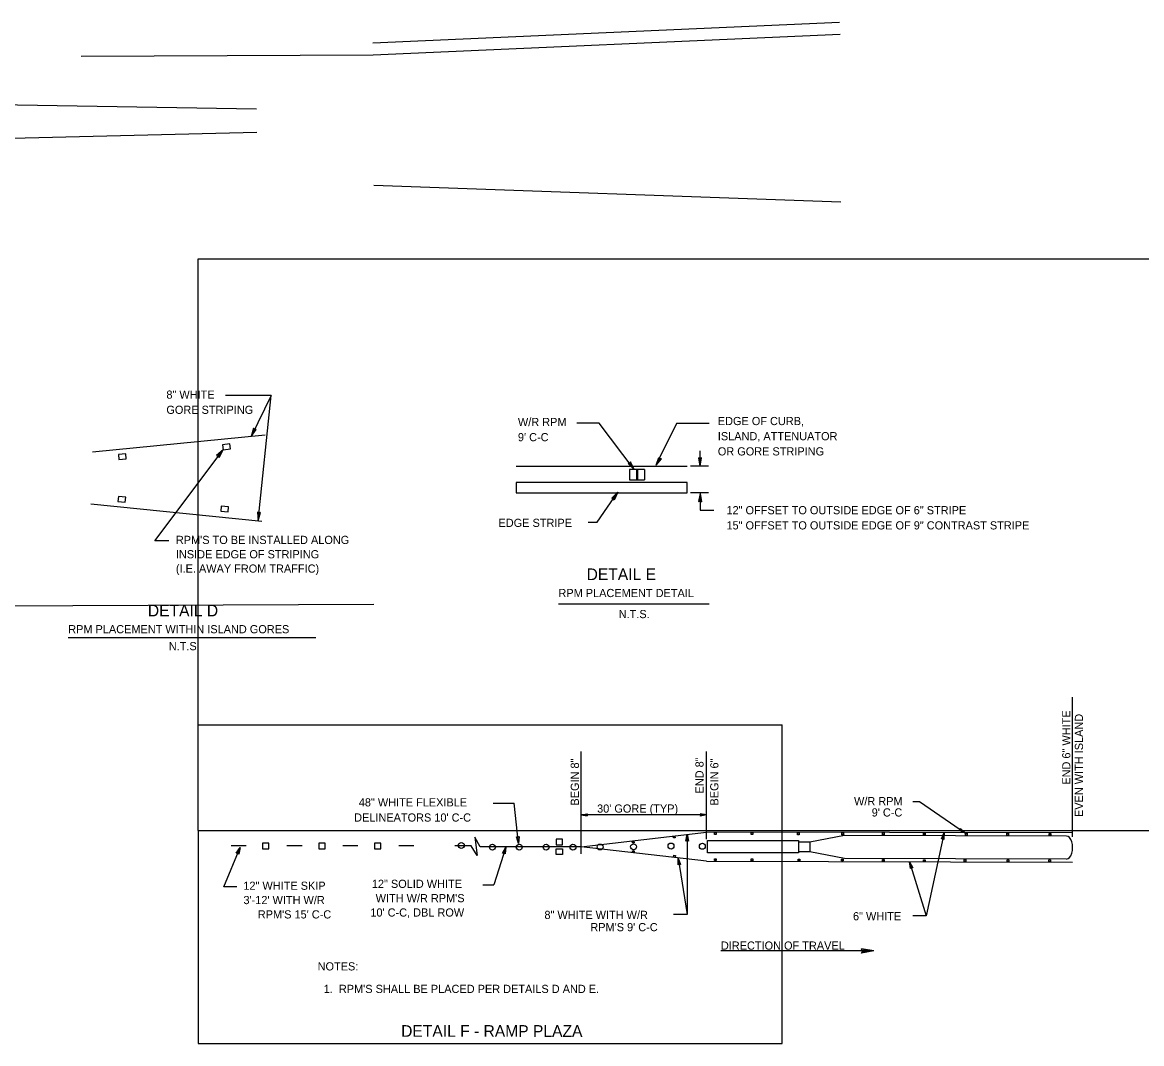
# Model space of a CAD drawing. Extents: x 583689 to 590775, y 1496016 to 1497365.
# Drawn here: x 587898 to 588857, y 1496490 to 1497365 of the extents above; entities that cross this region are included whole.
import ezdxf

# ---------------------------------------------------------------- set-up
doc = ezdxf.new("R2010")
doc.units = 0
for name, color, linetype in [('1', 7, 'Continuous'), ('10', 7, 'Continuous'), ('11', 7, 'Continuous'), ('12', 7, 'Continuous'), ('21', 7, 'Continuous'), ('32', 7, 'Continuous'), ('42', 7, 'Continuous'), ('5', 7, 'Continuous'), ('50', 7, 'Continuous'), ('52', 7, 'Continuous'), ('6', 7, 'Continuous'), ('63', 7, 'Continuous'), ('TextNotes', 7, 'Continuous'), ('TextShtNo', 7, 'Continuous')]:
    doc.layers.add(name, color=color, linetype=linetype)

msp = doc.modelspace()

# ---------------------------------------------------------------- linework, layer by layer
at = {"layer": '1'}
for points in [[(588075.82, 1497003.36), (588069.51, 1497002.74), (588069.93, 1496998.47), (588076.24, 1496999.09)], [(587986.62, 1496994.95), (587980.31, 1496994.33), (587980.73, 1496990.06), (587987.04, 1496990.68)], [(587986.66, 1496957.79), (587980.34, 1496958.42), (587979.91, 1496954.15), (587986.23, 1496953.52)], [(588074.73, 1496949.55), (588068.41, 1496950.18), (588067.98, 1496945.91), (588074.3, 1496945.28)]]:
    msp.add_lwpolyline(points, close=True, dxfattribs=at)
at = {"layer": '10'}
for p, q in [((588602.17, 1496667.88), (588572.63, 1496662.21)), ((588792.25, 1496667.38), (588602.17, 1496667.88)), ((588572.61, 1496654.03), (588562.86, 1496654.03)), ((588572.63, 1496662.21), (588562.89, 1496662.21)), ((588572.63, 1496662.21), (588572.61, 1496654.03)), ((588602.12, 1496648.21), (588572.61, 1496654.03)), ((588792.25, 1496647.71), (588602.12, 1496648.21))]:
    msp.add_line(p, q, dxfattribs=at)
msp.add_lwpolyline([(588562.89, 1496663.56), (588562.89, 1496652.96), (588484.88, 1496652.96), (588484.88, 1496663.56)], close=True, dxfattribs=at)
msp.add_ellipse((588792.25, 1496657.54), major_axis=(0, 9.84), ratio=0.545749, start_param=3.141593, end_param=6.283306, dxfattribs=at)
at = {"layer": '11'}
for p, q in [((588376.64, 1496658.15), (588484.04, 1496670.88)), ((588797.62, 1496670.05), (588484.04, 1496670.88)), ((588484, 1496645.83), (588376.64, 1496658.15)), ((588484, 1496645.83), (588797.62, 1496645))]:
    msp.add_line(p, q, dxfattribs=at)
for points in [[(588457.15, 1496665.93), (588455.71, 1496665.78), (588455.56, 1496667.22), (588457, 1496667.38)], [(588492.37, 1496668.81), (588490.92, 1496668.81), (588490.92, 1496670.43), (588492.37, 1496670.43)], [(588523.84, 1496668.7), (588522.39, 1496668.7), (588522.39, 1496670.33), (588523.84, 1496670.33)], [(588563.41, 1496668.52), (588561.96, 1496668.52), (588561.96, 1496670.15), (588563.41, 1496670.15)], [(588601.32, 1496668.41), (588599.87, 1496668.41), (588599.87, 1496670.03), (588601.32, 1496670.03)], [(588636.08, 1496668.49), (588634.63, 1496668.49), (588634.63, 1496670.12), (588636.08, 1496670.12)], [(588671.27, 1496668.35), (588669.82, 1496668.35), (588669.82, 1496669.98), (588671.27, 1496669.98)], [(588707.28, 1496668.13), (588705.83, 1496668.13), (588705.83, 1496669.76), (588707.28, 1496669.76)], [(588742.75, 1496668.13), (588741.3, 1496668.13), (588741.3, 1496669.76), (588742.75, 1496669.76)], [(588778.85, 1496668.09), (588777.4, 1496668.09), (588777.4, 1496669.72), (588778.85, 1496669.72)], [(588421.98, 1496661.7), (588420.54, 1496661.55), (588420.39, 1496662.99), (588421.83, 1496663.14)], [(588422.04, 1496653.27), (588420.6, 1496653.44), (588420.77, 1496654.88), (588422.21, 1496654.71)], [(588457.21, 1496649.39), (588455.77, 1496649.55), (588455.94, 1496650.99), (588457.38, 1496650.83)], [(588492.37, 1496646.32), (588490.92, 1496646.32), (588490.92, 1496647.95), (588492.37, 1496647.95)], [(588523.74, 1496646.21), (588522.29, 1496646.21), (588522.29, 1496647.84), (588523.74, 1496647.84)], [(588563.96, 1496646.06), (588562.51, 1496646.06), (588562.51, 1496647.69), (588563.96, 1496647.69)], [(588601.19, 1496646.06), (588599.74, 1496646.06), (588599.74, 1496647.69), (588601.19, 1496647.69)], [(588636.08, 1496645.83), (588634.63, 1496645.83), (588634.63, 1496647.46), (588636.08, 1496647.46)], [(588671.27, 1496645.53), (588669.82, 1496645.53), (588669.82, 1496647.16), (588671.27, 1496647.16)], [(588706.13, 1496645.7), (588704.68, 1496645.7), (588704.68, 1496647.33), (588706.13, 1496647.33)], [(588742.86, 1496645.28), (588741.41, 1496645.28), (588741.41, 1496646.91), (588742.86, 1496646.91)], [(588778.75, 1496645.38), (588777.3, 1496645.38), (588777.3, 1496647.01), (588778.75, 1496647.01)]]:
    msp.add_lwpolyline(points, close=True, dxfattribs=at)
for centre in [(588274.02, 1496659.33), (588300.66, 1496657.91), (588323.66, 1496657.91), (588346.66, 1496657.91), (588369.66, 1496657.91), (588392.87, 1496658.02), (588421.58, 1496658.23), (588453.63, 1496658.85), (588480.47, 1496658.64)]:
    msp.add_circle(centre, 2.54, dxfattribs=at)
at = {"layer": '12'}
for p, q in [((588106.1, 1497011), (587958.1, 1496996.48)), ((587956.6, 1496952.04), (588103.15, 1496937.28))]:
    msp.add_line(p, q, dxfattribs=at)
at = {"layer": '21'}
for p, q in [((588425, 1496981.64), (588425, 1496972.64)), ((588797.62, 1496666.66), (588797.57, 1496786.49)), ((588376.67, 1496652.28), (588376.63, 1496739.95)), ((588484.04, 1496664.71), (588484.01, 1496740)), ((588660.62, 1496696.92), (588666.5, 1496696.92)), ((588666.5, 1496696.92), (588705.83, 1496669.76)), ((588376.58, 1496685.58), (588381.78, 1496686.59)), ((588376.58, 1496685.58), (588381.58, 1496686.1)), ((588483.96, 1496685.58), (588376.58, 1496685.58)), ((588376.58, 1496685.58), (588381.82, 1496684.74)), ((588376.58, 1496685.58), (588381.6, 1496685.22)), ((588381.78, 1496686.59), (588381.4, 1496685.66)), ((588381.4, 1496685.66), (588381.82, 1496684.74)), ((588483.96, 1496685.58), (588478.73, 1496686.41)), ((588479.14, 1496685.49), (588478.73, 1496686.41)), ((588483.96, 1496685.58), (588478.76, 1496684.57)), ((588478.76, 1496684.57), (588479.14, 1496685.49)), ((588483.96, 1496685.58), (588478.95, 1496685.93)), ((588483.96, 1496685.58), (588478.96, 1496685.05)), ((588467.42, 1496668.91), (588467.39, 1496600.2)), ((588687.48, 1496670.34), (588672.18, 1496599.13)), ((588459.86, 1496648.6), (588467.39, 1496600.2)), ((588657.97, 1496645.37), (588672.18, 1496599.13)), ((588467.39, 1496600.2), (588455.89, 1496600.2)), ((588672.18, 1496599.13), (588660.68, 1496599.13)), ((588627.21, 1496569.04), (588523.47, 1496569.04)), ((588627.21, 1496569.04), (588616.75, 1496570.7)), ((588617.58, 1496568.88), (588616.75, 1496570.7)), ((588627.21, 1496569.04), (588616.81, 1496567.03)), ((588616.81, 1496567.03), (588617.58, 1496568.88)), ((588627.21, 1496569.04), (588617.19, 1496569.75)), ((588627.21, 1496569.04), (588617.21, 1496568))]:
    msp.add_line(p, q, dxfattribs=at)
at = {"layer": '32'}
for p, q in [((588290.14, 1496658.15), (588285.71, 1496666.59)), ((588285.71, 1496666.59), (588287.73, 1496650.86)), ((588089.69, 1496658.93), (588076.79, 1496658.93)), ((588137.59, 1496658.93), (588124.69, 1496658.93)), ((588185.48, 1496658.93), (588172.59, 1496658.93)), ((588233.38, 1496658.93), (588220.48, 1496658.93)), ((588282.49, 1496658.93), (588268.38, 1496658.93)), ((588287.73, 1496650.86), (588282.49, 1496658.93)), ((588376.64, 1496658.15), (588290.14, 1496658.15))]:
    msp.add_line(p, q, dxfattribs=at)
for points in [[(588360.83, 1496664.78), (588355.39, 1496664.78), (588355.39, 1496659.84), (588360.83, 1496659.84)], [(588109.31, 1496661.4), (588103.87, 1496661.4), (588103.87, 1496656.46), (588109.31, 1496656.46)], [(588157.55, 1496661.4), (588152.11, 1496661.4), (588152.11, 1496656.46), (588157.55, 1496656.46)], [(588205.1, 1496661.4), (588199.66, 1496661.4), (588199.66, 1496656.46), (588205.1, 1496656.46)], [(588360.83, 1496651.47), (588355.39, 1496651.47), (588355.39, 1496656.41), (588360.83, 1496656.41)]]:
    msp.add_lwpolyline(points, close=True, dxfattribs=at)
at = {"layer": '42'}
msp.add_line((588598.01, 1497364.63), (588198.12, 1497346.87), dxfattribs=at)
at = {"layer": '5'}
for p, q in [((588198.57, 1497336.88), (588598.45, 1497354.64)), ((587948.53, 1497335.77), (588198.57, 1497336.88)), ((588098.73, 1497290.4), (587598.69, 1497298.22)), ((587598.86, 1497258.23), (588098.81, 1497270.47)), ((588599.08, 1497210.65), (588199.06, 1497224.88)), ((588199.06, 1496865.96), (586110.22, 1496856.73))]:
    msp.add_line(p, q, dxfattribs=at)
at = {"layer": '50'}
for p, q in [((588111.31, 1497044.79), (588072.15, 1497044.81)), ((588111.31, 1497044.79), (588093.99, 1497009.81)), ((588099.91, 1496937.6), (588111.31, 1497044.79)), ((588392.06, 1497021.07), (588372.99, 1497021.08)), ((588422.17, 1496981.64), (588392.06, 1497021.07)), ((588458.36, 1497020.85), (588441.03, 1496985.87)), ((588486.35, 1497020.86), (588458.36, 1497020.85)), ((588011.42, 1496920.49), (588069.93, 1496998.47)), ((588441.03, 1496985.09), (588443.15, 1496991.87)), ((588441.03, 1496985.09), (588443.59, 1496991.32)), ((588441.03, 1496985.09), (588444.63, 1496990.79)), ((588441.03, 1496985.09), (588445.34, 1496990.74)), ((588444, 1496990.83), (588443.15, 1496991.87)), ((588445.34, 1496990.74), (588444, 1496990.83)), ((588478.5, 1496984.45), (588477.39, 1496991.47)), ((588478.61, 1496990.91), (588477.39, 1496991.47)), ((588478.5, 1496984.45), (588478.03, 1496991.17)), ((588478.5, 1496984.45), (588478.51, 1496997.56)), ((588478.5, 1496984.45), (588479.86, 1496991.42)), ((588478.5, 1496984.45), (588479.2, 1496991.15)), ((588479.86, 1496991.42), (588478.61, 1496990.91)), ((588320.98, 1496984.47), (588467.54, 1496984.47)), ((588418.33, 1496986.84), (588417.02, 1496986.54)), ((588422.17, 1496981.64), (588417.02, 1496986.54)), ((588422.17, 1496981.64), (588417.72, 1496986.69)), ((588418, 1496981.64), (588418, 1496972.64)), ((588431, 1496981.64), (588418, 1496981.64)), ((588419.01, 1496988.01), (588418.33, 1496986.84)), ((588422.17, 1496981.64), (588418.66, 1496987.39)), ((588422.17, 1496981.64), (588419.01, 1496988.01)), ((588424, 1496981.64), (588424, 1496972.64)), ((588431, 1496981.64), (588431, 1496972.64)), ((588485.61, 1496984.48), (588470.34, 1496984.48)), ((588418, 1496972.64), (588431, 1496972.64)), ((588390.33, 1496936.37), (588408.15, 1496961.94)), ((588485.62, 1496961.41), (588470.35, 1496961.4)), ((588478.5, 1496960.92), (588477.15, 1496953.94)), ((588478.5, 1496960.92), (588477.8, 1496954.21)), ((588478.5, 1496961.4), (588478.51, 1496946.76)), ((588478.5, 1496960.92), (588479.62, 1496953.9)), ((588478.5, 1496960.92), (588478.97, 1496954.2)), ((588477.15, 1496953.94), (588478.39, 1496954.46)), ((588478.39, 1496954.46), (588479.62, 1496953.9)), ((588478.51, 1496946.76), (588490.26, 1496946.75)), ((588382.61, 1496936.37), (588390.33, 1496936.37)), ((588023.54, 1496920.49), (588011.42, 1496920.49)), ((588357.23, 1496866.43), (588486.29, 1496866.42)), ((587937.37, 1496837.41), (588149.42, 1496837.41)), ((588301.23, 1496695.54), (588319.27, 1496695.54)), ((588323.12, 1496661.14), (588319.27, 1496695.54)), ((588070.62, 1496623.86), (588084.54, 1496657.73)), ((588312.2, 1496657.91), (588301.82, 1496625.62)), ((588292.48, 1496625.62), (588301.82, 1496625.62)), ((588081.9, 1496623.86), (588070.62, 1496623.86))]:
    msp.add_line(p, q, dxfattribs=at)
msp.add_lwpolyline([(588467.54, 1496970.4), (588320.98, 1496970.4), (588320.98, 1496961.39), (588467.54, 1496961.39)], close=True, dxfattribs=at)
at = {"layer": '52'}
for p, q in [((588096, 1497016.91), (588093.99, 1497009.81)), ((588093.99, 1497009.81), (588098.46, 1497015.69)), ((588096.96, 1497015.81), (588096, 1497016.91)), ((588098.46, 1497015.69), (588096.96, 1497015.81)), ((588069.93, 1496998.47), (588064.45, 1496993.51)), ((588064.45, 1496993.51), (588065.9, 1496993.11)), ((588065.9, 1496993.11), (588066.65, 1496991.86)), ((588066.65, 1496991.86), (588069.93, 1496998.47)), ((588100.62, 1496944.26), (588099.33, 1496944.95)), ((588099.33, 1496944.95), (588099.91, 1496937.6)), ((588099.91, 1496937.6), (588102.07, 1496944.66)), ((588102.07, 1496944.66), (588100.62, 1496944.26)), ((588701.42, 1496672.81), (588701.68, 1496673.95)), ((588701.68, 1496673.95), (588705.83, 1496669.76)), ((588323.12, 1496661.14), (588321.36, 1496666.78)), ((588321.36, 1496666.78), (588322.53, 1496666.47)), ((588322.53, 1496666.47), (588323.55, 1496667.03)), ((588323.55, 1496667.03), (588323.12, 1496661.14)), ((588466.34, 1496663.11), (588467.42, 1496668.91)), ((588467.42, 1496663.55), (588466.34, 1496663.11)), ((588467.42, 1496668.91), (588468.54, 1496663.11)), ((588468.54, 1496663.11), (588467.42, 1496663.55)), ((588685.2, 1496664.9), (588687.48, 1496670.34)), ((588686.35, 1496665.1), (588685.2, 1496664.9)), ((588687.36, 1496664.44), (588686.35, 1496665.1)), ((588687.48, 1496670.34), (588687.36, 1496664.44)), ((588700.43, 1496672.14), (588701.42, 1496672.81)), ((588705.83, 1496669.76), (588700.43, 1496672.14)), ((588081.34, 1496652.77), (588084.54, 1496657.73)), ((588084.54, 1496657.73), (588083.37, 1496651.94)), ((588309.39, 1496652.72), (588312.2, 1496657.91)), ((588312.2, 1496657.91), (588311.49, 1496652.05)), ((588082.51, 1496652.77), (588081.34, 1496652.77)), ((588083.37, 1496651.94), (588082.51, 1496652.77)), ((588310.56, 1496652.81), (588309.39, 1496652.72)), ((588311.49, 1496652.05), (588310.56, 1496652.81)), ((588459.68, 1496642.71), (588459.86, 1496648.6)), ((588459.86, 1496648.6), (588461.86, 1496643.05)), ((588657.97, 1496645.37), (588660.75, 1496640.16)), ((588658.64, 1496639.51), (588657.97, 1496645.37)), ((588460.68, 1496643.31), (588459.68, 1496642.71)), ((588461.86, 1496643.05), (588460.68, 1496643.31)), ((588659.55, 1496640.25), (588658.64, 1496639.51)), ((588660.75, 1496640.16), (588659.55, 1496640.25))]:
    msp.add_line(p, q, dxfattribs=at)
msp.add_lwpolyline([(588408.15, 1496961.94), (588404.92, 1496955.3), (588404.21, 1496956.46), (588402.86, 1496956.8)], close=True, dxfattribs=at)
at = {"layer": '63'}
for p, q in [((588048.77, 1497162.09), (589534.15, 1497162.09)), ((588048.77, 1496672.09), (588048.77, 1497162.09)), ((588048.77, 1496762.59), (588548.77, 1496762.59)), ((588548.77, 1496489.55), (588548.77, 1496762.59)), ((588048.77, 1496672.09), (589534.15, 1496672.09)), ((588048.77, 1496672.09), (588048.77, 1496489.55)), ((588048.77, 1496489.55), (588548.77, 1496489.55))]:
    msp.add_line(p, q, dxfattribs=at)
at = {"layer": 'TextShtNo'}
msp.add_line((588523.47, 1496569.04), (588496.34, 1496569.04), dxfattribs=at)

# ---------------------------------------------------------------- texts
at = {"layer": '21'}
for s, p in [("30' GORE (TYP)", (588390.33, 1496687.48)), ('W/R RPM', (588610.38, 1496693.82)), ("9' C-C", (588625.49, 1496684.16)), ('6" WHITE', (588609.48, 1496595.24)), ('DIRECTION OF TRAVEL', (588496.34, 1496570.06))]:
    msp.add_text(s, height=7, dxfattribs=at).set_placement(p)
at = {"layer": '50'}
for s, height, p in [('8" WHITE', 7, (588021.44, 1497042.16)), ('GORE STRIPING', 7, (588021.44, 1497029.16)), ('W/R RPM', 7, (588322.51, 1497018.72)), ('EDGE OF CURB,', 7, (588493.71, 1497019.54)), ("9' C-C", 7, (588322.51, 1497005.72)), ('ISLAND, ATTENUATOR', 7, (588493.71, 1497006.54)), ('OR GORE STRIPING', 7, (588493.71, 1496993.54)), ('12" OFFSET TO OUTSIDE EDGE OF 6" STRIPE ', 7, (588501.12, 1496943.14)), ('15" OFFSET TO OUTSIDE EDGE OF 9" CONTRAST STRIPE', 7, (588501.12, 1496930.14)), ("RPM'S TO BE INSTALLED ALONG", 7, (588029.57, 1496917.67)), ('INSIDE EDGE OF STRIPING', 7, (588029.57, 1496905.39)), ('(I.E. AWAY FROM TRAFFIC)', 7, (588029.57, 1496893.11)), ('DETAIL E', 10, (588381.31, 1496886.71)), ('DETAIL D', 10, (588005.58, 1496855.62)), ('48" WHITE FLEXIBLE', 7, (588186.23, 1496692.8)), ("DELINEATORS 10' C-C ", 7, (588182.26, 1496679.8)), ('12" WHITE SKIP ', 7, (588087.36, 1496621.36)), ('12" SOLID WHITE', 7, (588197.42, 1496622.98)), ("3'-12' WITH W/R ", 7, (588087.46, 1496609.08)), ("WITH W/R RPM'S", 7, (588200.68, 1496610.7)), ("RPM'S 15' C-C", 7, (588099.74, 1496596.8)), ("10' C-C, DBL ROW", 7, (588196.14, 1496598.42)), ('8" WHITE WITH W/R', 7, (588345.22, 1496596.36)), ("RPM'S 9' C-C", 7, (588384.54, 1496585.86))]:
    msp.add_text(s, height=height, dxfattribs=at).set_placement(p)
for s, rotation, p in [('EDGE STRIPE', 0, (588305.9, 1496932.29)), ('RPM PLACEMENT DETAIL', 359.99873, (588357.23, 1496872.16)), ('N.T.S.', 0, (588408.83, 1496854.13)), ('RPM PLACEMENT WITHIN ISLAND GORES', 359.99873, (587937.37, 1496841.17)), ('N.T.S.', 359.99873, (588023.48, 1496826.64)), ('END 6" WHITE', 90, (588795.67, 1496711.44)), ('EVEN WITH ISLAND', 90, (588806.47, 1496683.72)), ('BEGIN 8"', 90, (588374.73, 1496693.54)), ('END 8"', 90, (588481.5, 1496703.92)), ('BEGIN 6"', 90, (588494.22, 1496693.59))]:
    msp.add_text(s, height=7, rotation=rotation, dxfattribs=at).set_placement(p)
at = {"layer": '6'}
msp.add_text('DETAIL F - RAMP PLAZA', height=10, rotation=359.99873, dxfattribs=at).set_placement((588222.48, 1496495.37))
at = {"layer": 'TextNotes'}
for s, p in [('NOTES:', (588150.97, 1496552.26)), ("  1.  RPM'S SHALL BE PLACED PER DETAILS D AND E.", (588150.97, 1496532.95))]:
    msp.add_text(s, height=7, dxfattribs=at).set_placement(p)

doc.saveas('drawing.dxf')
